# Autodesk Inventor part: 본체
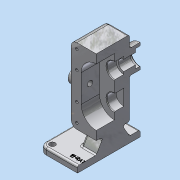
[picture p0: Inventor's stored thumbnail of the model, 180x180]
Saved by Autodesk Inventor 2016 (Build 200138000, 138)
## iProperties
Created: 2020-04
Part Number: 본체
Material: 알루미늄 6061
Document SubType Name: Modeling
Designer: MIRAE
Density: 2.7 g/cm^3
Appearance: 알루미늄 - 평지
Mass: 1472.54 g
Surface Area: 818.394 cm^2
Volume: 545.387 cm^3
Author: MIRAE
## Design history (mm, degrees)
sketch "스케치1"
  geometry: L1 (-60, 70)-(60, 70); L2 (60, 70)-(60, -30); L3 (60, -30)-(-60, -30); L4 (-60, -30)-(-60, 70); 2 further points
  constraints: 8 end point, 2 parallel, 1 horizontal, 1 midpoint, 1 perpendicular, 1 vertical alignment
  dimensions: "d4" = 120 distance of L2.end L3.end; "d5" = 100 distance of L1.end L2.end; "d6" = 70 distance from line of point (0, 0) L1
extrude "돌출1" new body sketch "스케치1" distance "d2" = 10; taper "d3" = 0 deg
sketch "스케치2"
  geometry: L1 (40, 150)-(-40, 150); L2 (-40, 150)-(-40, 30); L3 (-40, 30)-(40, 30); L4 (40, 30)-(40, 150); L5 (-60, 0)-(60, 0) reference; 3 further points
  constraints: 8 end point, 2 midpoint, 2 parallel, 1 horizontal, 1 perpendicular, 1 vertical alignment
  dimensions: "d7" = 80 distance of L1.start L1.end; "d8" = 150 distance between parallel lines of L5 L1; "d9" = 120 distance of L3.end L1.start
extrude "돌출2" join sketch "스케치2" distance "d10" = 53; taper "d11" = 0 deg
sketch "스케치3"
  geometry: L1 (0, 30)-(53, 30) reference; L2 (11.547, 30)-(0, 10); L3 (41.453, 30)-(53, 10); L4 (70, 10)-(-30, 10) reference; L5 (11.547, 30)-(41.453, 30); L6 (0, 10)-(53, 10); L7 (70, 0)-(70, 10) reference; 1 further point
  constraints: 8 end point, 4 point on line, 1 collinear, 1 horizontal
  dimensions: "d12" = 60 deg angle of L4 L2; "d13" = 60 deg angle of L4 L3; "d14" = 17 distance from line of L7 L3.end; "d15" = 53 distance of L3.end L2.end
extrude "돌출3" join sketch "스케치3" stored distance "d16" = 48; taper "d17" = 0 deg
sketch "스케치4"
  geometry: L1 (0, 112)-(0, 68); L2 (-24, 112)-(-24, 68); L3 (24, 68)-(24, 112); L4 (60, 0)-(-60, 0) reference; A1 r 24 centre (0, 112) between (24, 112) and (-24, 112); A2 r 24 centre (0, 68) between (-24, 68) and (24, 68); 3 further points
  constraints: 8 end point, 4 point on circle, 4 tangent, 2 centre point, 2 midpoint, 1 parallel, 1 vertical, 1 vertical alignment
  dimensions: "d18" = 24 radius of A1; "d19" = 44 distance of L1.start L1.end; "d20" = 90 distance from line of L4 point (0, 90)
extrude "돌출4" cut sketch "스케치4" distance "d21" = 29; taper "d22" = 0 deg
sketch "스케치6"
  geometry: C1 r 19 at (0, -112); A1 r 24 centre (0, -112) between (-24, -112) and (24, -112) reference; 1 further point
  constraints: 1 centre point, 1 coincident
  dimensions: "d27" = 38 diameter of C1
extrude "돌출5" join sketch "스케치6" distance "d28" = 17; taper "d29" = 0 deg
sketch "스케치5"
  geometry: L1 (29, 112)-(29, 136) reference; L2 (29, 112)-(70, 112); L3 (0, 112)-(29, 112) reference; L4 (29, 112)-(29, 124.5); L5 (29, 124.5)-(44, 124.5); L6 (44, 124.5)-(44, 120.5); L7 (44, 120.5)-(62.7, 120.5); L8 (62.7, 120.5)-(62.7, 126); L9 (62.7, 126)-(70, 126); L10 (70, 126)-(70, 112); L11 (70, 93)-(70, 131) reference; 1 further point
  constraints: 16 end point, 3 perpendicular, 2 horizontal, 1 midpoint, 1 point on line, 1 vertical
  dimensions: "d23" = 25 diameter of L5 L2; "d24" = 17 diameter of L7 L2; "d25" = 28 diameter of L9 L2; "d30" = 15 distance of L4.end L5.end; "d31" = 7.3 distance between parallel lines of L10 L8
revolve "회전1" sketch "스케치5" stored, may be unused: angle "d32" = 90 deg
hole "구멍1" diameter "d35" = 25; stored, may be unused: countersink angle "d39" = 90 deg, drill point angle "d41" = 0 deg; dims "d33" = 10, "d34" = 10, "d36" = 6, "d37" = 4, "d38" = 2, "d40" = 15
sketch "스케치7"
  geometry: L1 (150, 70)-(150, -30) reference; L2 (0, 0)-(120, 0) reference; C1 r 11 at (60, 14); 1 further point
  constraints: 1 centre point
  dimensions: "d42" = 22 diameter of C1; "d43" = 90 distance from line of L1 C1.centre; "d44" = 14 distance from line of C1.centre L2
extrude "돌출6" join sketch "스케치7" distance "d45" = 8; taper "d46" = 0 deg
hole "구멍2" diameter "d49" = 8.376; stored, may be unused: countersink angle "d53" = 90 deg, drill point angle "d55" = 118 deg; dims "d47" = 10, "d48" = 10, "d50" = 20, "d51" = 4, "d52" = 2, "d54" = 27.3
fillet "모깎기1" dims "d56" = 10, "d57" = 9
hole "구멍3" diameter "d60" = 9; stored, may be unused: countersink angle "d64" = 90 deg, drill point angle "d66" = 118 deg; dims "d58" = 10, "d59" = 10, "d61" = 20, "d62" = 4, "d63" = 2, "d65" = 27.3
hole "구멍4" diameter "d75" = 4.134; stored, may be unused: countersink angle "d79" = 90 deg, drill point angle "d81" = 118 deg; dims "d73" = 10, "d74" = 10, "d76" = 10, "d77" = 4, "d78" = 2, "d80" = 12
hole "구멍5" diameter "d90" = 4.134; stored, may be unused: countersink angle "d94" = 90 deg, drill point angle "d96" = 118 deg; dims "d88" = 10, "d89" = 10, "d91" = 10, "d92" = 4, "d93" = 2, "d95" = 12
fillet "모깎기2" dims "d103" = 0.5
chamfer "모따기1" distance "d104" = 0.7; stored, may be unused: second distance "d105" = 2, angle "d106" = 30 deg
sketch "스케치8"
  geometry: L1 (-60, 60)-(-60, -20) reference; L2 (-50, -30)-(50, -30) reference; 2 further points
  constraints: 1 other
  dimensions: "d107" = 60 distance from line of L1 point (0, -20); "d108" = 10 distance from line of L2 point (0, -20)
feature "엠보싱1" sketch "스케치8" dims "d12" = 60 deg, "d13" = 60 deg, "d14" = 17, "d15" = 53, "d109" = 0.5, "d110" = 0
fillet "모깎기3" dims "d111" = 3
fillet "모깎기4" dims "d112" = 3
fillet "모깎기5" dims "d113" = 3
chamfer "모따기2" distance "d114" = 1; stored, may be unused: second distance "d115" = 2, angle "d116" = 30 deg
feature "분할1"
node "솔리드1"
mirror "대칭1"
pattern_linear "직사각형 패턴1" dims "d69" = 100
pattern_linear "직사각형 패턴2" dims "d84" = 62, "d87" = 29
pattern_linear "직사각형 패턴3" dims "d99" = 62, "d102" = 29
